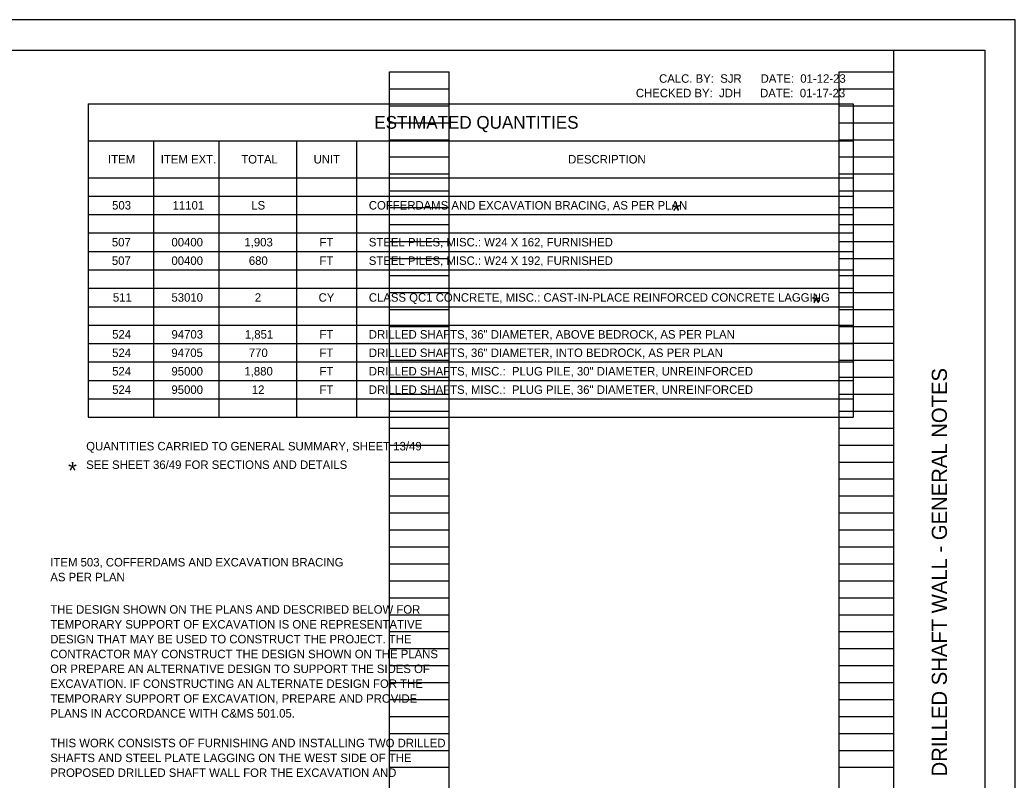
# Model space of a CAD drawing. Extents: x 0 to 34, y 0 to 22.
# Drawn here: x 17.58 to 34, y 9.45 to 22 of the extents above; entities that cross this region are included whole.
import ezdxf

# ---------------------------------------------------------------- set-up
doc = ezdxf.new("R2010")
doc.units = 0
for name, color, linetype in [('BR_P_Gen_Text', 7, 'Continuous'), ('SC_Scratch9', 7, 'Continuous'), ('SH_Border', 7, 'Continuous'), ('SH_Cut_Line', 7, 'Continuous'), ('SH_Data', 7, 'Continuous')]:
    doc.layers.add(name, color=color, linetype=linetype)

msp = doc.modelspace()

# ---------------------------------------------------------------- linework, layer by layer
at = {"layer": 'SC_Scratch9'}
for p, q in [((23.68, 0.98), (23.68, 21.14)), ((23.68, 21.14), (24.66, 21.14)), ((24.66, 0.98), (24.66, 21.14)), ((31.1, 0.98), (31.1, 21.14)), ((31.1, 21.14), (32, 21.14)), ((32, 0.98), (32, 21.14)), ((23.68, 20.86), (24.66, 20.86)), ((31.1, 20.86), (32, 20.86)), ((23.68, 20.58), (24.66, 20.58)), ((31.1, 20.58), (32, 20.58)), ((23.68, 20.3), (24.66, 20.3)), ((31.1, 20.3), (32, 20.3)), ((23.68, 20.02), (24.66, 20.02)), ((31.1, 20.02), (32, 20.02)), ((23.68, 19.74), (24.66, 19.74)), ((31.1, 19.74), (32, 19.74)), ((23.68, 19.46), (24.66, 19.46)), ((31.1, 19.46), (32, 19.46)), ((23.68, 19.18), (24.66, 19.18)), ((31.1, 19.18), (32, 19.18)), ((23.68, 18.9), (24.66, 18.9)), ((31.1, 18.9), (32, 18.9)), ((23.68, 18.62), (24.66, 18.62)), ((31.1, 18.62), (32, 18.62)), ((23.68, 18.34), (24.66, 18.34)), ((31.1, 18.34), (32, 18.34)), ((23.68, 18.06), (24.66, 18.06)), ((31.1, 18.06), (32, 18.06)), ((23.68, 17.78), (24.66, 17.78)), ((31.1, 17.78), (32, 17.78)), ((23.68, 17.5), (24.66, 17.5)), ((31.1, 17.5), (32, 17.5)), ((23.68, 17.22), (24.66, 17.22)), ((31.1, 17.22), (32, 17.22)), ((23.68, 16.94), (24.66, 16.94)), ((31.1, 16.94), (32, 16.94)), ((23.68, 16.66), (24.66, 16.66)), ((31.1, 16.66), (32, 16.66)), ((23.68, 16.38), (24.66, 16.38)), ((31.1, 16.38), (32, 16.38)), ((23.68, 16.1), (24.66, 16.1)), ((31.1, 16.1), (32, 16.1)), ((23.68, 15.82), (24.66, 15.82)), ((31.1, 15.82), (32, 15.82)), ((23.68, 15.54), (24.66, 15.54)), ((31.1, 15.54), (32, 15.54)), ((23.68, 15.26), (24.66, 15.26)), ((31.1, 15.26), (32, 15.26)), ((23.68, 14.98), (24.66, 14.98)), ((31.1, 14.98), (32, 14.98)), ((23.68, 14.7), (24.66, 14.7)), ((31.1, 14.7), (32, 14.7)), ((23.68, 14.42), (24.66, 14.42)), ((31.1, 14.42), (32, 14.42)), ((23.68, 14.14), (24.66, 14.14)), ((31.1, 14.14), (32, 14.14)), ((23.68, 13.86), (24.66, 13.86)), ((31.1, 13.86), (32, 13.86)), ((23.68, 13.58), (24.66, 13.58)), ((31.1, 13.58), (32, 13.58)), ((23.68, 13.3), (24.66, 13.3)), ((31.1, 13.3), (32, 13.3)), ((23.68, 13.02), (24.66, 13.02)), ((31.1, 13.02), (32, 13.02)), ((23.68, 12.74), (24.66, 12.74)), ((31.1, 12.74), (32, 12.74)), ((23.68, 12.46), (24.66, 12.46)), ((31.1, 12.46), (32, 12.46)), ((23.68, 12.18), (24.66, 12.18)), ((31.1, 12.18), (32, 12.18)), ((23.68, 11.9), (24.66, 11.9)), ((31.1, 11.9), (32, 11.9)), ((23.68, 11.62), (24.66, 11.62)), ((31.1, 11.62), (32, 11.62)), ((23.68, 11.34), (24.66, 11.34)), ((31.1, 11.34), (32, 11.34)), ((23.68, 11.06), (24.66, 11.06)), ((31.1, 11.06), (32, 11.06)), ((23.68, 10.78), (24.66, 10.78)), ((31.1, 10.78), (32, 10.78)), ((23.68, 10.5), (24.66, 10.5)), ((31.1, 10.5), (32, 10.5)), ((23.68, 10.22), (24.66, 10.22)), ((31.1, 10.22), (32, 10.22)), ((23.68, 9.94), (24.66, 9.94)), ((31.1, 9.94), (32, 9.94)), ((23.68, 9.66), (24.66, 9.66)), ((31.1, 9.66), (32, 9.66))]:
    msp.add_line(p, q, dxfattribs=at)
at = {"layer": 'SH_Border'}
msp.add_line((32, 0.5), (32, 21.5), dxfattribs=at)
msp.add_lwpolyline([(1.5, 21.5), (33.5, 21.5), (33.5, 0.5), (1.5, 0.5)], close=True, dxfattribs=at)
at = {"layer": 'SH_Cut_Line'}
msp.add_lwpolyline([(0, 0), (34, 0), (34, 22), (0, 22)], close=True, dxfattribs=at)
at = {"layer": 'SH_Data'}
for p, q in [((18.708, 20.612), (31.326, 20.612)), ((18.708, 20.612), (18.708, 15.439)), ((31.326, 20.612), (31.326, 15.439)), ((18.708, 20.004), (31.326, 20.004)), ((19.786, 20.004), (19.786, 15.439)), ((20.864, 20.004), (20.864, 15.439)), ((22.145, 20.004), (22.145, 15.439)), ((23.134, 20.004), (23.134, 15.439)), ((18.708, 19.395), (31.326, 19.395)), ((18.708, 19.091), (31.326, 19.091)), ((18.708, 18.786), (31.326, 18.786)), ((18.708, 18.482), (31.326, 18.482)), ((18.708, 18.178), (31.326, 18.178)), ((18.708, 17.873), (31.326, 17.873)), ((18.708, 17.569), (31.326, 17.569)), ((18.708, 17.265), (31.326, 17.265)), ((18.708, 16.96), (31.326, 16.96)), ((18.708, 16.656), (31.326, 16.656)), ((18.708, 16.352), (31.326, 16.352)), ((18.708, 16.047), (31.326, 16.047)), ((18.708, 15.743), (31.326, 15.743)), ((18.708, 15.439), (31.326, 15.439))]:
    msp.add_line(p, q, dxfattribs=at)

# ---------------------------------------------------------------- texts
at = {"layer": 'BR_P_Gen_Text'}
for s, height, p in [('CALC. BY:  SJR      DATE:  01-12-23', 0.14, (28.126, 20.962)), ('CHECKED BY:  JDH      DATE:  01-17-23', 0.14, (27.743, 20.722)), ('*', 0.28, (28.335, 18.707)), ('*', 0.28, (30.646, 17.185)), ('QUANTITIES CARRIED TO GENERAL SUMMARY, SHEET 13/49', 0.14, (18.674, 14.892)), ('*', 0.28, (18.375, 14.421)), ('SEE SHEET 36/49 FOR SECTIONS AND DETAILS', 0.14, (18.674, 14.586)), ('ITEM 503, COFFERDAMS AND EXCAVATION BRACING', 0.14, (18.082, 12.976)), ('AS PER PLAN', 0.14, (18.082, 12.731)), ('THE DESIGN SHOWN ON THE PLANS AND DESCRIBED BELOW FOR', 0.14, (18.081, 12.196)), ('TEMPORARY SUPPORT OF EXCAVATION IS ONE REPRESENTATIVE', 0.14, (18.081, 11.951)), ('DESIGN THAT MAY BE USED TO CONSTRUCT THE PROJECT. THE ', 0.14, (18.081, 11.706)), ('CONTRACTOR MAY CONSTRUCT THE DESIGN SHOWN ON THE PLANS', 0.14, (18.081, 11.461)), ('OR PREPARE AN ALTERNATIVE DESIGN TO SUPPORT THE SIDES OF ', 0.14, (18.081, 11.216)), ('EXCAVATION. IF CONSTRUCTING AN ALTERNATE DESIGN FOR THE', 0.14, (18.081, 10.971)), ('TEMPORARY SUPPORT OF EXCAVATION, PREPARE AND PROVIDE ', 0.14, (18.081, 10.726)), ('PLANS IN ACCORDANCE WITH C&MS 501.05.', 0.14, (18.081, 10.481)), ('THIS WORK CONSISTS OF FURNISHING AND INSTALLING TWO DRILLED ', 0.14, (18.081, 9.991)), ('SHAFTS AND STEEL PLATE LAGGING ON THE WEST SIDE OF THE ', 0.14, (18.081, 9.746)), ('PROPOSED DRILLED SHAFT WALL FOR THE EXCAVATION AND ', 0.14, (18.081, 9.501))]:
    msp.add_text(s, height=height, dxfattribs=at).set_placement(p)
at = {"layer": 'SH_Data'}
for s, height, p in [('ESTIMATED QUANTITIES', 0.21, (23.427, 20.203)), ('ITEM', 0.14, (19.034, 19.629)), ('ITEM EXT.', 0.14, (19.904, 19.629)), ('TOTAL', 0.14, (21.232, 19.629)), ('UNIT', 0.14, (22.426, 19.629)), ('DESCRIPTION', 0.14, (26.626, 19.629)), ('503', 0.14, (19.101, 18.869)), ('11101', 0.14, (20.1, 18.869)), ('LS', 0.14, (21.397, 18.869)), ('COFFERDAMS AND EXCAVATION BRACING, AS PER PLAN', 0.14, (23.337, 18.869)), ('507', 0.14, (19.097, 18.26)), ('00400', 0.14, (20.08, 18.26)), ('1,903', 0.14, (21.284, 18.26)), ('FT', 0.14, (22.523, 18.26)), ('STEEL PILES, MISC.: W24 X 162, FURNISHED', 0.14, (23.337, 18.26)), ('507', 0.14, (19.097, 17.955)), ('00400', 0.14, (20.08, 17.955)), ('680', 0.14, (21.357, 17.955)), ('FT', 0.14, (22.523, 17.955)), ('STEEL PILES, MISC.: W24 X 192, FURNISHED', 0.14, (23.337, 17.955)), ('511', 0.14, (19.114, 17.347)), ('53010', 0.14, (20.08, 17.347)), ('2', 0.14, (21.455, 17.347)), ('CY', 0.14, (22.508, 17.347)), ('CLASS QC1 CONCRETE, MISC.: CAST-IN-PLACE REINFORCED CONCRETE LAGGING', 0.14, (23.337, 17.347)), ('524', 0.14, (19.102, 16.738)), ('94703', 0.14, (20.081, 16.738)), ('1,851', 0.14, (21.291, 16.738)), ('FT', 0.14, (22.523, 16.738)), ('DRILLED SHAFTS, 36" DIAMETER, ABOVE BEDROCK, AS PER PLAN', 0.14, (23.337, 16.738)), ('524', 0.14, (19.102, 16.434)), ('94705', 0.14, (20.079, 16.434)), ('770', 0.14, (21.357, 16.434)), ('FT', 0.14, (22.523, 16.434)), ('DRILLED SHAFTS, 36" DIAMETER, INTO BEDROCK, AS PER PLAN', 0.14, (23.337, 16.434)), ('524', 0.14, (19.102, 16.129)), ('95000', 0.14, (20.08, 16.129)), ('1,880', 0.14, (21.284, 16.129)), ('FT', 0.14, (22.523, 16.129)), ('DRILLED SHAFTS, MISC.:  PLUG PILE, 30" DIAMETER, UNREINFORCED', 0.14, (23.337, 16.129)), ('524', 0.14, (19.102, 15.825)), ('95000', 0.14, (20.08, 15.825)), ('12', 0.14, (21.406, 15.825)), ('FT', 0.14, (22.523, 15.825)), ('DRILLED SHAFTS, MISC.:  PLUG PILE, 36" DIAMETER, UNREINFORCED', 0.14, (23.337, 15.825))]:
    msp.add_text(s, height=height, dxfattribs=at).set_placement(p)
msp.add_text('DRILLED SHAFT WALL - GENERAL NOTES', height=0.25, rotation=90, dxfattribs=at).set_placement((32.875, 9.509))

doc.saveas('drawing.dxf')
